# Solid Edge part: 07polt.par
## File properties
Author: User
Template: Iso Metric Part.par
Last saved by: User
Revision: 2
Application: Solid Edge
Accuracy: 0,990
Username: User
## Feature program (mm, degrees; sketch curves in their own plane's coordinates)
sketch for "unnamed Protrusion 1" plane through (0, 0, 0) normal (0, 0, 1) x-axis (1, 0, 0)
  circle centre (0, 0) radius 0.175
extrude "unnamed Protrusion 1" add finite 0.5 along +normal
logasc func "Lip_Groove_1"  LipOrGrooveWidth = 0.35 mm; LipOrGrooveHeight = 0.1 mm
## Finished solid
Body 1: solid body, 5 faces, 4 edges, 0 vertices.
  Faces by surface: plane 3, cylinder 2
  Edges by curve: circle 4
Bounding box of the edges (mm): 0.350 x 0.350 x 0.500, from (-0.175, -0.175, 0) to (0.175, 0.175, 0.5).
Cylindrical faces by radius (mm): R0.075 x1, R0.175 x1
Planar faces by outward normal: +z 1, -z 2
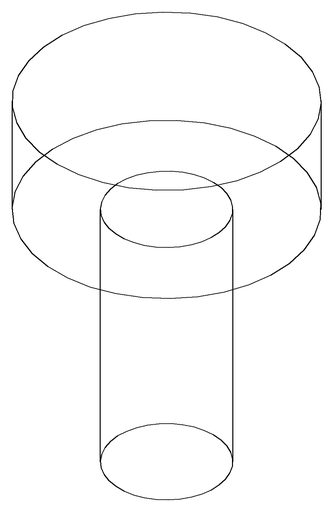
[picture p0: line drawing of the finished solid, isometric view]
